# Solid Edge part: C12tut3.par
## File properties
Author: Ashutosh-CADCIM
Template: ansi inch part.par
Last saved by: Ashutosh-CADCIM
Revision: 1
Application: Solid Edge
Accuracy: 0.990
Username: Ashutosh-CADCIM
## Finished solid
Body 1: solid body, 12 faces, 16 edges, 6 vertices.
  Faces by surface: plane 8, cylinder 4
  Edges by curve: circle 8, line 7, ellipse 1
Bounding box of the edges (mm): 31.750 x 82.478 x 31.750, from (-15.875, -77.9793, -15.875) to (15.875, 4.4987, 15.875).
Cylindrical faces by radius (mm): R5.5944 x1, R6.35 x1, R7.9375 x1, R15.875 x1
Planar faces by outward normal: +x 1, +y 1, -x 1, -y 4, oblique 1
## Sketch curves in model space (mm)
line (-22.318, -0.2404, 12.6982) -> (-22.2829, -4.9679, 7.9011)
line (-22.2618, -77.9738, 5.0232) -> (-22.2673, -0.1897, 5.7686)
line (-22.1798, -77.8918, -6.1649) -> (-22.1842, -0.1066, -5.5759)
line (-22.2202, -89.5716, -0.6561) -> (-22.2258, 15.4021, 0.1128)
line (-22.2678, -68.4546, 5.8486) -> (-22.2673, -77.9793, 5.7788)
line (-22.2673, -77.9793, 5.7788) -> (-22.1743, -77.8863, -6.9205)
line (-22.1748, -68.3616, -6.8507) -> (-22.1743, -77.8863, -6.9205)
line (-22.3413, -0.2637, 15.8731) -> (-22.1087, -0.0311, -15.8752)
line (-22.3415, 4.4987, 15.908) -> (-22.3413, -0.2637, 15.8731)
line (-22.3415, 4.4987, 15.908) -> (-22.109, 4.7312, -15.8403)
line (-22.109, 4.7312, -15.8403) -> (-22.1087, -0.0311, -15.8752)
line (-22.1669, -0.0893, -7.9382) -> (-22.1632, -68.3499, -8.4381)
line (-22.2831, -0.2055, 7.936) -> (-22.2795, -68.4662, 7.436)
line (-22.2795, -68.4662, 7.436) -> (-22.1632, -68.3499, -8.4381)
line (0, 0, 22.225) -> (0, 0, -22.225)
line (22.225, 0, 0) -> (-22.225, 0, 0)
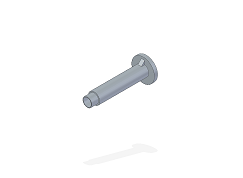
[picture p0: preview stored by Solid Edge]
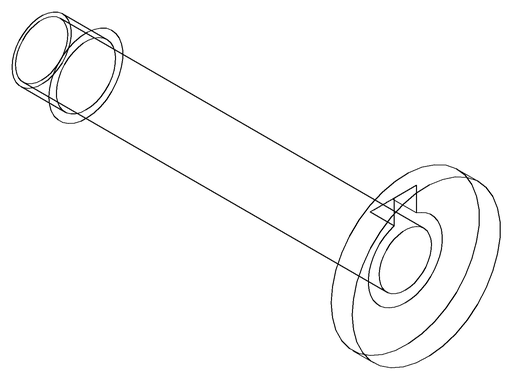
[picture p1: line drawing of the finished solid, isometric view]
